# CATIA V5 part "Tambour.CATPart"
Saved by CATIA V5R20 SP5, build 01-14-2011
Part number: Skl_Tambour
Publications: "Plan xy", "Axe_pivot_tambour/gouv"
Bounding box of the stored display mesh (mm): x -121.136 to 121.136, y 0 to 419.951, z -10 to 150
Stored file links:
  U:\2A\CFAO\dossier sans titre\Tambour.CATPart
  U:\2A\CFAO\dossier sans titre\Skl_gouvernail.CATProduct
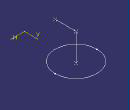
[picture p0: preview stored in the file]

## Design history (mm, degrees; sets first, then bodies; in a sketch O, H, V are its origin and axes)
Set1
  Point1 "Point.24": linked copy from another document
  Point2 "Point.25": linked copy from another document
  Point3 "Point.23": linked copy from another document
Body1 (main body)
  Line1: type PtPt, FirstPoint Point1, SecondPoint Point2
  Line2 "Axe_pivot_tambour/gouv": type PtPt, FirstPoint Point1, SecondPoint Point3
  Sketch1 on xy-plane, origin (0, 0, 0), H (1, 0, 0), V (0, 1, 0)
    circle A1 centre (0, 298.8638) radius 121.1365
    point P1 (0, 298.8638)
    reference projected point E1 (0, 298.8638) from Point3
    reference projected point E2 (0, 177.7273) from Point2
    coincidence: P1 E1, A1 E2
